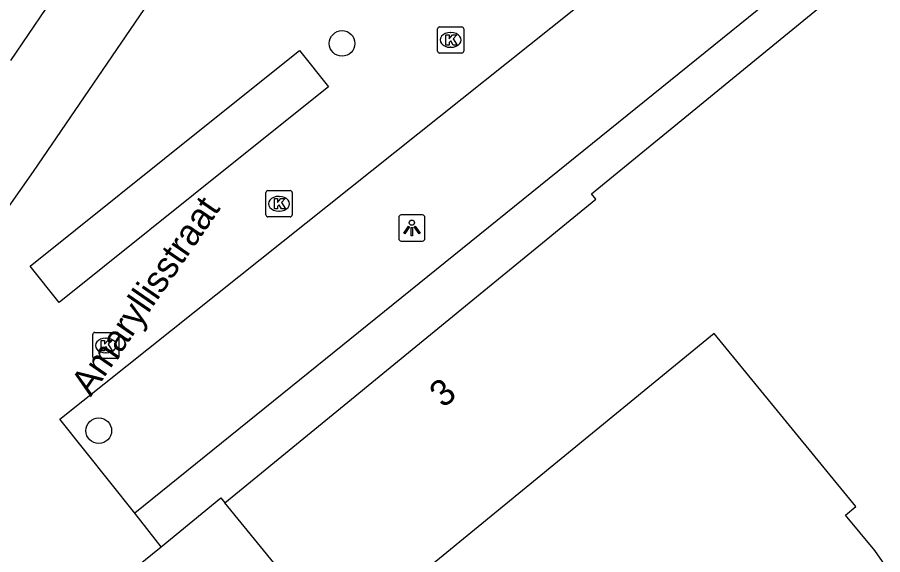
# Model space of a CAD drawing. Extents: x 161882 to 162509, y 381687 to 382379.
# Drawn here: x 162144.53 to 162177.57, y 382017.01 to 382037.54 of the extents above; entities that cross this region are included whole.
import ezdxf

# ---------------------------------------------------------------- set-up
doc = ezdxf.new("R2010")
doc.units = 0
for name, color, linetype in [('IMGEO_Boom', 7, 'Continuous'), ('IMGEO_Kolk', 7, 'Continuous'), ('IMGEO_Lichtpunt', 7, 'Continuous'), ('IMGEO_Openbare_ruimte_label', 7, 'Continuous'), ('IMGEO_Pand', 7, 'Continuous'), ('IMGEO_Pand_nummerreeks', 7, 'Continuous'), ('IMGEO_Parkeervlak_open', 7, 'Continuous'), ('IMGEO_Rijbaan_lokaal_open', 7, 'Continuous'), ('IMGEO_Woonerf_open', 7, 'Continuous')]:
    doc.layers.add(name, color=color, linetype=linetype)

msp = doc.modelspace()

# ---------------------------------------------------------------- linework, layer by layer
at = {"layer": 'IMGEO_Boom'}
for centre in [(162156.933, 382036.541), (162147.644, 382021.748)]:
    msp.add_circle(centre, 0.489, dxfattribs=at)
at = {"layer": 'IMGEO_Kolk'}
for p, q in [((162160.578, 382036.248), (162160.578, 382037.1)), ((162160.653, 382037.174), (162161.505, 382037.174)), ((162161.066, 382036.954), (162161.091, 382036.954)), ((162161.579, 382037.1), (162161.579, 382036.248)), ((162161.089, 382036.394), (162161.064, 382036.394)), ((162161.505, 382036.174), (162160.653, 382036.174)), ((162154.026, 382029.992), (162154.026, 382030.844)), ((162154.101, 382030.918), (162154.953, 382030.918)), ((162154.514, 382030.698), (162154.539, 382030.698)), ((162155.027, 382030.844), (162155.027, 382029.992)), ((162154.537, 382030.138), (162154.512, 382030.138)), ((162154.953, 382029.918), (162154.101, 382029.918)), ((162147.413, 382024.574), (162147.413, 382025.426)), ((162147.488, 382025.5), (162148.34, 382025.5)), ((162148.414, 382025.426), (162148.414, 382024.574)), ((162147.901, 382025.28), (162147.926, 382025.28)), ((162147.924, 382024.72), (162147.899, 382024.72)), ((162148.34, 382024.5), (162147.488, 382024.5))]:
    msp.add_line(p, q, dxfattribs=at)
for points in [[(162160.578, 382036.248), (162160.578, 382037.1)], [(162160.653, 382037.174), (162161.505, 382037.174)], [(162161.579, 382037.1), (162161.579, 382036.248)], [(162160.899, 382036.874), (162161.022, 382036.874), (162161.022, 382036.723), (162161.152, 382036.874), (162161.316, 382036.874), (162161.17, 382036.723), (162161.323, 382036.474), (162161.171, 382036.474), (162161.086, 382036.638), (162161.022, 382036.571), (162161.022, 382036.474), (162160.899, 382036.474), (162160.899, 382036.874)], [(162161.505, 382036.174), (162160.653, 382036.174)], [(162154.026, 382029.992), (162154.026, 382030.844)], [(162154.101, 382030.918), (162154.953, 382030.918)], [(162154.347, 382030.618), (162154.47, 382030.618), (162154.47, 382030.467), (162154.6, 382030.618), (162154.764, 382030.618), (162154.618, 382030.467), (162154.771, 382030.218), (162154.619, 382030.218), (162154.534, 382030.382), (162154.47, 382030.315), (162154.47, 382030.218), (162154.347, 382030.218), (162154.347, 382030.618)], [(162155.027, 382030.844), (162155.027, 382029.992)], [(162154.953, 382029.918), (162154.101, 382029.918)], [(162147.413, 382024.574), (162147.413, 382025.426)], [(162147.488, 382025.5), (162148.34, 382025.5)], [(162148.414, 382025.426), (162148.414, 382024.574)], [(162147.734, 382025.2), (162147.857, 382025.2), (162147.857, 382025.049), (162147.987, 382025.2), (162148.151, 382025.2), (162148.005, 382025.049), (162148.158, 382024.8), (162148.006, 382024.8), (162147.921, 382024.964), (162147.857, 382024.897), (162147.857, 382024.8), (162147.734, 382024.8), (162147.734, 382025.2)], [(162148.34, 382024.5), (162147.488, 382024.5)]]:
    msp.add_lwpolyline(points, dxfattribs=at)
for centre, start, end in [((162160.655, 382037.098), 91.552, 178.448), ((162160.655, 382037.098), 91.552, 178.448), ((162161.503, 382037.098), 1.552, 88.448), ((162161.503, 382037.098), 1.552, 88.448), ((162160.655, 382036.25), 181.552, 268.448), ((162160.655, 382036.25), 181.552, 268.448), ((162161.503, 382036.25), 271.552, 358.448), ((162161.503, 382036.25), 271.552, 358.448), ((162154.103, 382030.842), 91.552, 178.448), ((162154.103, 382030.842), 91.552, 178.448), ((162154.951, 382030.842), 1.552, 88.448), ((162154.951, 382030.842), 1.552, 88.448), ((162154.103, 382029.994), 181.552, 268.448), ((162154.103, 382029.994), 181.552, 268.448), ((162154.951, 382029.994), 271.552, 358.448), ((162154.951, 382029.994), 271.552, 358.448), ((162147.49, 382025.424), 91.552, 178.448), ((162147.49, 382025.424), 91.552, 178.448), ((162148.338, 382025.424), 1.552, 88.448), ((162148.338, 382025.424), 1.552, 88.448), ((162147.49, 382024.576), 181.552, 268.448), ((162147.49, 382024.576), 181.552, 268.448), ((162148.338, 382024.576), 271.552, 358.448), ((162148.338, 382024.576), 271.552, 358.448)]:
    msp.add_arc(centre, 0.0765, start, end, dxfattribs=at)
for centre, major_axis, ratio, start_param, end_param in [((162161.065, 382036.674), (-0.387, 0.002), 0.722429, 4.712389, 7.853982), ((162161.09, 382036.674), (-0.39, 0.002), 0.717154, 1.570796, 4.712389), ((162154.513, 382030.418), (-0.387, 0.002), 0.722429, 4.712389, 7.853982), ((162154.538, 382030.418), (-0.39, 0.002), 0.717154, 1.570796, 4.712389), ((162147.9, 382025), (-0.387, 0.002), 0.722429, 4.712389, 7.853982), ((162147.925, 382025), (-0.39, 0.002), 0.717154, 1.570796, 4.712389)]:
    msp.add_ellipse(centre, major_axis=major_axis, ratio=ratio, start_param=start_param, end_param=end_param, dxfattribs=at)
at = {"layer": 'IMGEO_Lichtpunt'}
for p, q in [((162160, 382029.99), (162159.192, 382029.99)), ((162160, 382029.99), (162159.192, 382029.99)), ((162159.098, 382029.895), (162159.098, 382029.088)), ((162159.098, 382029.895), (162159.098, 382029.088)), ((162160.094, 382029.088), (162160.094, 382029.895)), ((162160.094, 382029.088), (162160.094, 382029.895)), ((162159.192, 382028.994), (162160, 382028.994)), ((162159.192, 382028.994), (162160, 382028.994))]:
    msp.add_line(p, q, dxfattribs=at)
for points in [[(162159.472, 382029.559), (162159.511, 382029.531), (162159.323, 382029.269), (162159.285, 382029.296), (162159.472, 382029.559)], [(162159.574, 382029.511), (162159.621, 382029.511), (162159.621, 382029.189), (162159.574, 382029.189), (162159.574, 382029.511)], [(162159.684, 382029.531), (162159.722, 382029.558), (162159.909, 382029.296), (162159.87, 382029.268), (162159.684, 382029.531)]]:
    msp.add_lwpolyline(points, dxfattribs=at)
msp.add_circle((162159.597, 382029.693), 0.0994, dxfattribs=at)
for centre, start, end in [((162159.192, 382029.895), 90, 180), ((162159.192, 382029.895), 90, 180), ((162160, 382029.895), 0, 90), ((162160, 382029.895), 0, 90), ((162159.192, 382029.088), 180, 270), ((162159.192, 382029.088), 180, 270), ((162160, 382029.088), 270, 0), ((162160, 382029.088), 270, 360)]:
    msp.add_arc(centre, 0.0946, start, end, dxfattribs=at)
at = {"layer": 'IMGEO_Pand'}
for points in [[(162152.462, 382018.996), (162166.618, 382030.597), (162166.459, 382030.79), (162181.344, 382042.988), (162191.177, 382030.989), (162192.732, 382029.062), (162193.295, 382028.375), (162193.718, 382027.859)], [(162147.645, 382040.864), (162144.269, 382035.889)], [(162193.718, 382027.859), (162192.868, 382027.162), (162178.511, 382015.397), (162177.271, 382017.167), (162176.155, 382018.528), (162176.553, 382018.855), (162171.139, 382025.462), (162160.651, 382016.868), (162156.783, 382013.698), (162156.187, 382014.426)], [(162150.019, 382017.317), (162152.304, 382019.19), (162152.462, 382018.996)], [(162156.187, 382014.426), (162154.446, 382016.562), (162152.462, 382018.996)], [(162152.994, 382011.81), (162149.249, 382016.379), (162149.098, 382016.563), (162150.019, 382017.317)]]:
    msp.add_lwpolyline(points, dxfattribs=at)
at = {"layer": 'IMGEO_Parkeervlak_open'}
for points in [[(162149.021, 382018.603), (162146.162, 382022.187), (162178.575, 382048.051)], [(162151.885, 382033.535), (162155.305, 382036.274), (162156.416, 382034.886), (162152.997, 382032.147), (162146.129, 382026.647), (162145.018, 382028.035), (162151.885, 382033.535)]]:
    msp.add_lwpolyline(points, dxfattribs=at)
at = {"layer": 'IMGEO_Rijbaan_lokaal_open'}
for points in [[(162181.319, 382044.718), (162149.021, 382018.603)], [(162150.019, 382017.317), (162149.021, 382018.603)]]:
    msp.add_lwpolyline(points, dxfattribs=at)
at = {"layer": 'IMGEO_Woonerf_open'}
msp.add_lwpolyline([(162177.425, 382078.945), (162145.138, 382031.653), (162139.862, 382024.142), (162139.84, 382024.123)], dxfattribs=at)

# ---------------------------------------------------------------- texts
at = {"layer": 'IMGEO_Openbare_ruimte_label'}
msp.add_text('Amaryllisstraat', height=1, rotation=55.4679, dxfattribs=at).set_placement((162147.338, 382023.017))
at = {"layer": 'IMGEO_Pand_nummerreeks'}
msp.add_text('3', height=1, rotation=39.3336, dxfattribs=at).set_placement((162160.792, 382022.59))

doc.saveas('drawing.dxf')
